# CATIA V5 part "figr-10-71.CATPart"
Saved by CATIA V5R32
Part number: Part1
Bounding box of the stored display mesh (mm): x -45.985 to 45.985, y -45.985 to 45.985, z -55 to 3.515
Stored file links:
  D:\PROJECTS\Project 2022\CATIA V5 6R 2022\Resources\Part Files\c10_catia_v5_6r2022_prt\c10_catia_v5_6r2022_prt\figr-10-71.CATPart
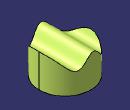
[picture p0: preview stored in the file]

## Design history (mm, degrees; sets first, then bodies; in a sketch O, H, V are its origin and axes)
Set1
  Sketch1 on xy-plane, origin (0, 0, 0), H (-1, 0, 0), V (0, -1, 0)
    circle A1 centre (0, 0) radius 45.985
  Extrude1: Element1 Sketch1, Lim1 56, Lim2 55, Direction xy-plane
  Sketch2 on zx-plane, origin (0, 0, 0), H (1, 0, 0), V (0, 0, -1)
    spline S1 through (-80.5635, 24.8913) (-73.6025, 19.8803) (-54.8525, -3.3629) (-35.1982, 19.8803) (-2.6271, -1.6506) (16.6996, 17.2854) (52.4104, -6.7877) (63.5409, 1.5862)
  Extrude2: Element1 Sketch2, Lim1 72, Lim2 69, Direction Sketch1.V
  Split1: ToCut Extrude1, Cutting Extrude2
  Trim1: Element1 Extrude1, Element2 Extrude2
  Trim2: Element1 Extrude1, Element2 Extrude2
Body1 (main body)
